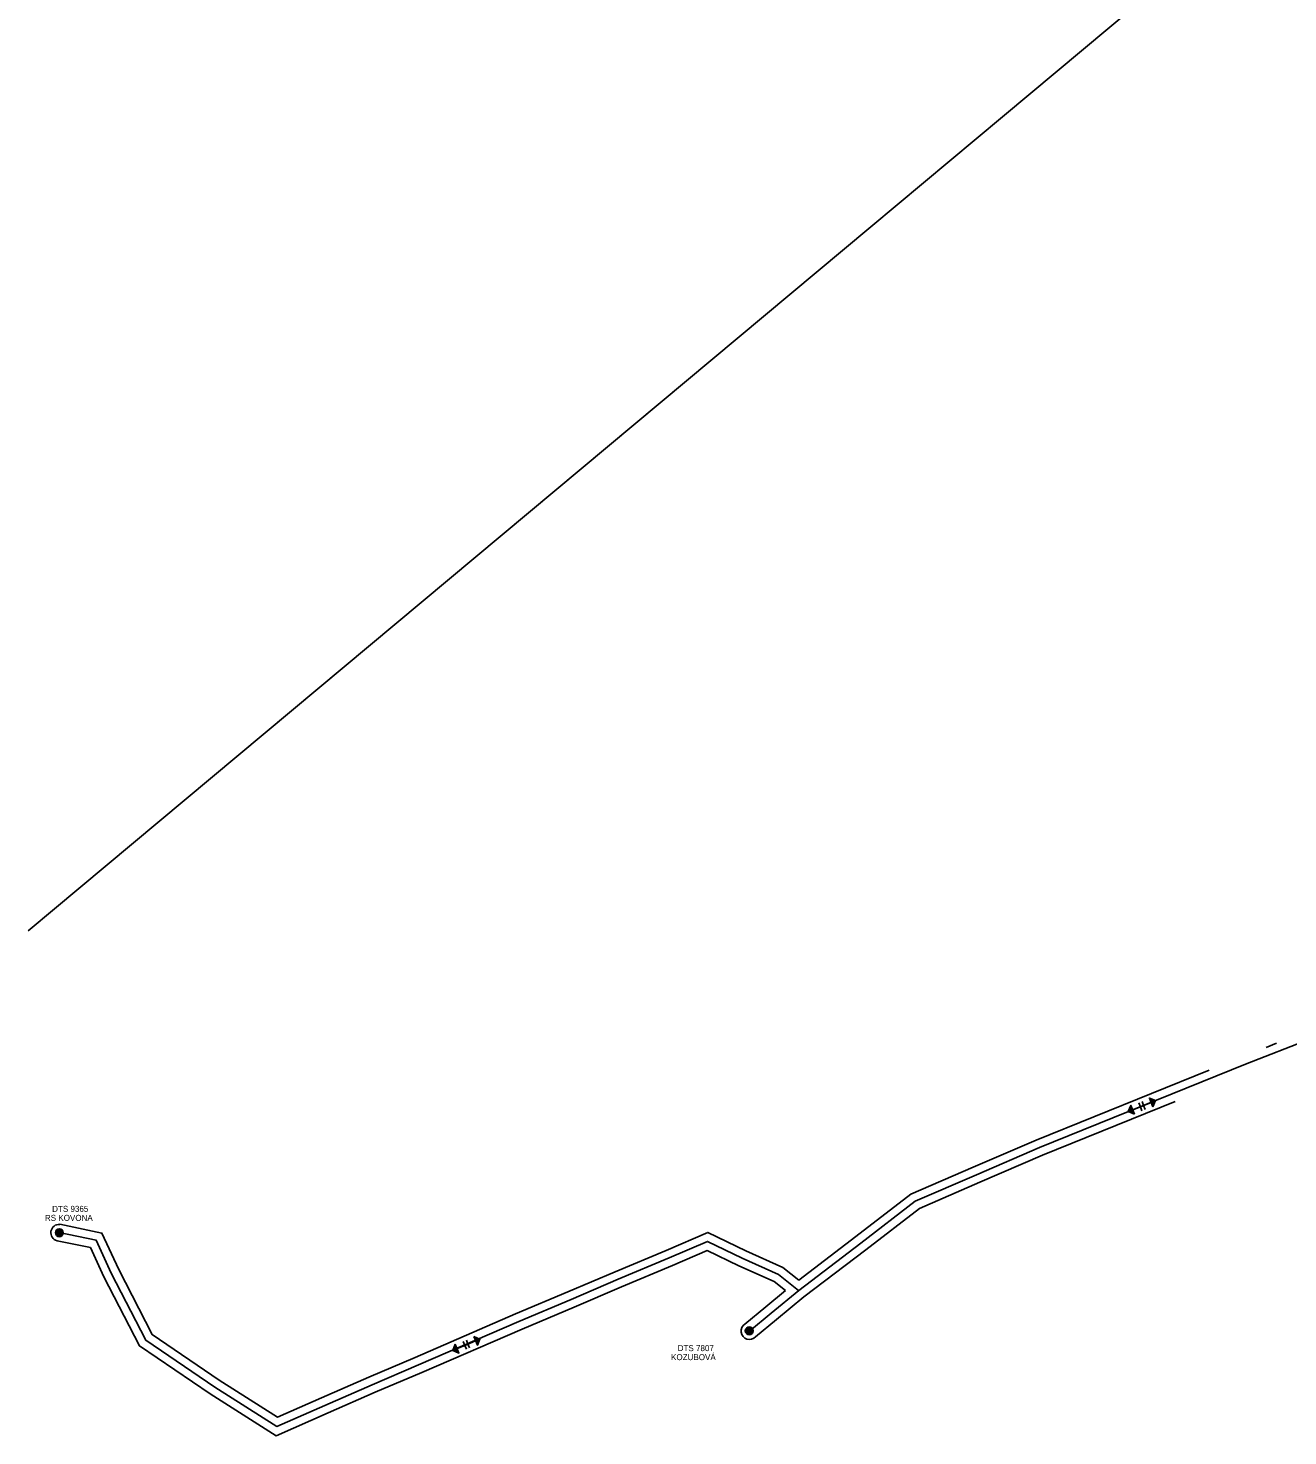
# Model space of a CAD drawing. Extents: x -444841 to -429545, y -1135312 to -1129851.
# Drawn here: x -444841 to -443164, y -1134006 to -1132132 of the extents above; entities that cross this region are included whole.
import ezdxf

# ---------------------------------------------------------------- set-up
doc = ezdxf.new("R2010")
doc.units = 0
for name, color, linetype in [('Vrstva 10', 7, 'Continuous'), ('Vrstva 11', 7, 'Continuous'), ('Vrstva 13', 7, 'Continuous'), ('Vrstva 15', 7, 'Continuous'), ('Vrstva 59', 7, 'Continuous')]:
    doc.layers.add(name, color=color, linetype=linetype)

msp = doc.modelspace()

# ---------------------------------------------------------------- linework, layer by layer
at = {"layer": 'Vrstva 10'}
for p, q in [((-443360.7, -1133567.6), (-443362.8, -1133562.4)), ((-443356.3, -1133565.8), (-443358.4, -1133560.6)), ((-443354.2, -1133571), (-443356.3, -1133565.8)), ((-443358.6, -1133572.8), (-443360.7, -1133567.6)), ((-444261.9, -1133880.1), (-444259.7, -1133885.3)), ((-444259.7, -1133885.3), (-444257.5, -1133890.4)), ((-444257.5, -1133878.2), (-444255.3, -1133883.4)), ((-444255.3, -1133883.4), (-444253.1, -1133888.6))]:
    msp.add_line(p, q, dxfattribs=at)
for points in [[(-442655.5, -1133000.4), (-442743.1, -1133037.4), (-442861.3, -1133223.2), (-442916.9, -1133291.7), (-442985.2, -1133371.5), (-443039.7, -1133433.2), (-443134.2, -1133477.2), (-443220.6, -1133510.9), (-443495.1, -1133621.9), (-443578.9, -1133658), (-443660.4, -1133693.4), (-443732.6, -1133749.2), (-443815.3, -1133812), (-443852, -1133842.2), (-443880.9, -1133866.1)], [(-443346.2, -1133561.7), (-443358.5, -1133566.7), (-443370.9, -1133571.7)], [(-443815.4, -1133812.1), (-443842.2, -1133790.8), (-443890.4, -1133769.1), (-443936.6, -1133746.8), (-443987.5, -1133768.8), (-444055.4, -1133797.2), (-444118.2, -1133824), (-444187.7, -1133853.3), (-444321.1, -1133911.2), (-444383, -1133937.5), (-444445.6, -1133965), (-444509.7, -1133993.1), (-444592.3, -1133940.6), (-444683.8, -1133878.3), (-444729.9, -1133789.1), (-444750, -1133745.3), (-444799.2, -1133735.1)], [(-444269.8, -1133889.5), (-444257.5, -1133884.3), (-444245.2, -1133879.2)]]:
    msp.add_lwpolyline(points, dxfattribs=at)
for points in [[(-443368.5, -1133577.5), (-443376.7, -1133574), (-443373.2, -1133565.8)], [(-443343.9, -1133567.5), (-443348.6, -1133555.9), (-443340.4, -1133559.3)], [(-443343.8, -1133565.7), (-443347.3, -1133557.2), (-443341.3, -1133559.7)], [(-443343.8, -1133563.9), (-443346, -1133558.5), (-443342.2, -1133560.1)], [(-443343.8, -1133562), (-443344.7, -1133559.8), (-443343.1, -1133560.4)], [(-443369.8, -1133576.2), (-443375.8, -1133573.7), (-443373.3, -1133567.7)], [(-443371.1, -1133574.9), (-443374.9, -1133573.3), (-443373.3, -1133569.5)], [(-443372.4, -1133573.6), (-443374, -1133572.9), (-443373.3, -1133571.3)], [(-444272.2, -1133883.7), (-444267.3, -1133895.3), (-444275.6, -1133892)], [(-444247.7, -1133873.4), (-444239.4, -1133876.7), (-444242.8, -1133885)], [(-444246.4, -1133874.6), (-444240.4, -1133877.1), (-444242.8, -1133883.1)], [(-444245.1, -1133875.9), (-444241.3, -1133877.5), (-444242.8, -1133881.3)], [(-444243.8, -1133877.2), (-444242.2, -1133877.9), (-444242.8, -1133879.5)], [(-444272.2, -1133885.5), (-444268.6, -1133894), (-444274.6, -1133891.6)], [(-444272.2, -1133887.4), (-444269.9, -1133892.7), (-444273.7, -1133891.2)], [(-444272.2, -1133889.2), (-444271.2, -1133891.5), (-444272.8, -1133890.8)]]:
    msp.add_lwpolyline(points, close=True, dxfattribs=at)
at = {"layer": 'Vrstva 11'}
for centre, radius in [((-444799, -1133735.2), 5.25), ((-444799, -1133735.2), 4.55), ((-444799, -1133735.2), 3.85), ((-444799, -1133735.2), 3.15), ((-444799, -1133735.2), 2.45), ((-444799, -1133735.2), 1.75), ((-444799, -1133735.2), 1.05), ((-444799, -1133735.2), 0.35), ((-443881.1, -1133865.8), 5.25), ((-443881.1, -1133865.8), 4.55), ((-443881.1, -1133865.8), 3.85), ((-443881.1, -1133865.8), 3.15), ((-443881.1, -1133865.8), 2.45), ((-443881.1, -1133865.8), 1.75), ((-443881.1, -1133865.8), 1.05), ((-443881.1, -1133865.8), 0.35)]:
    msp.add_circle(centre, radius, dxfattribs=at)
at = {"layer": 'Vrstva 15'}
for points in [[(-443179.4, -1133483), (-443193.5, -1133488.5)], [(-443269, -1133518.6), (-443499.4, -1133611.8), (-443583.3, -1133647.9), (-443666, -1133683.9), (-443739.3, -1133740.4), (-443815.3, -1133798.2)], [(-443872.8, -1133873.6), (-443845, -1133850.7), (-443808.4, -1133820.6), (-443726, -1133757.9), (-443654.7, -1133703), (-443574.5, -1133668.1), (-443490.9, -1133632.1), (-443314.5, -1133560.7)], [(-443815.3, -1133798.2), (-443836.5, -1133781.4), (-443885.7, -1133759.2), (-443936.3, -1133734.7), (-443991.8, -1133758.7), (-444059.7, -1133787.1), (-444122.5, -1133813.8), (-444192, -1133843.2), (-444325.4, -1133901.1), (-444387.4, -1133927.4), (-444450, -1133955), (-444508.7, -1133980.7), (-444586.3, -1133931.4), (-444675.3, -1133870.8), (-444720, -1133784.3), (-444742.3, -1133735.7), (-444798.5, -1133724)], [(-444802.1, -1133745.8), (-444757.7, -1133754.9), (-444739.8, -1133793.9), (-444692.3, -1133885.8), (-444598.4, -1133949.8), (-444510.6, -1134005.6), (-444441.2, -1133975.1), (-444378.7, -1133947.6), (-444316.8, -1133921.3), (-444183.3, -1133863.4), (-444113.9, -1133834.1), (-444051.1, -1133807.3), (-443983.2, -1133778.9), (-443936.9, -1133758.9), (-443895, -1133779.1), (-443848, -1133800.3), (-443832.9, -1133812.3)], [(-443832.9, -1133812.3), (-443859, -1133833.7), (-443887, -1133856.8)]]:
    msp.add_lwpolyline(points, dxfattribs=at)
for centre, start, end in [((-444799.2, -1133735.1), 85.967, 255.278), ((-443880.9, -1133866.1), 123.2072, 317.2524)]:
    msp.add_arc(centre, 11.1, start, end, dxfattribs=at)
at = {"layer": 'Vrstva 59'}
msp.add_lwpolyline([(-441161.7, -1130258), (-444840.5, -1133333.5)], dxfattribs=at)

# ---------------------------------------------------------------- texts
at = {"layer": 'Vrstva 13'}
for s, p in [('RS KOVONA', (-444818.2, -1133719.4)), ('DTS 9365', (-444808.6, -1133707.4)), ('DTS 7807', (-443976.3, -1133892.8)), ('KOZUBOVÁ', (-443985.1, -1133904.8))]:
    msp.add_text(s, height=8, dxfattribs=at).set_placement(p)

doc.saveas('drawing.dxf')
